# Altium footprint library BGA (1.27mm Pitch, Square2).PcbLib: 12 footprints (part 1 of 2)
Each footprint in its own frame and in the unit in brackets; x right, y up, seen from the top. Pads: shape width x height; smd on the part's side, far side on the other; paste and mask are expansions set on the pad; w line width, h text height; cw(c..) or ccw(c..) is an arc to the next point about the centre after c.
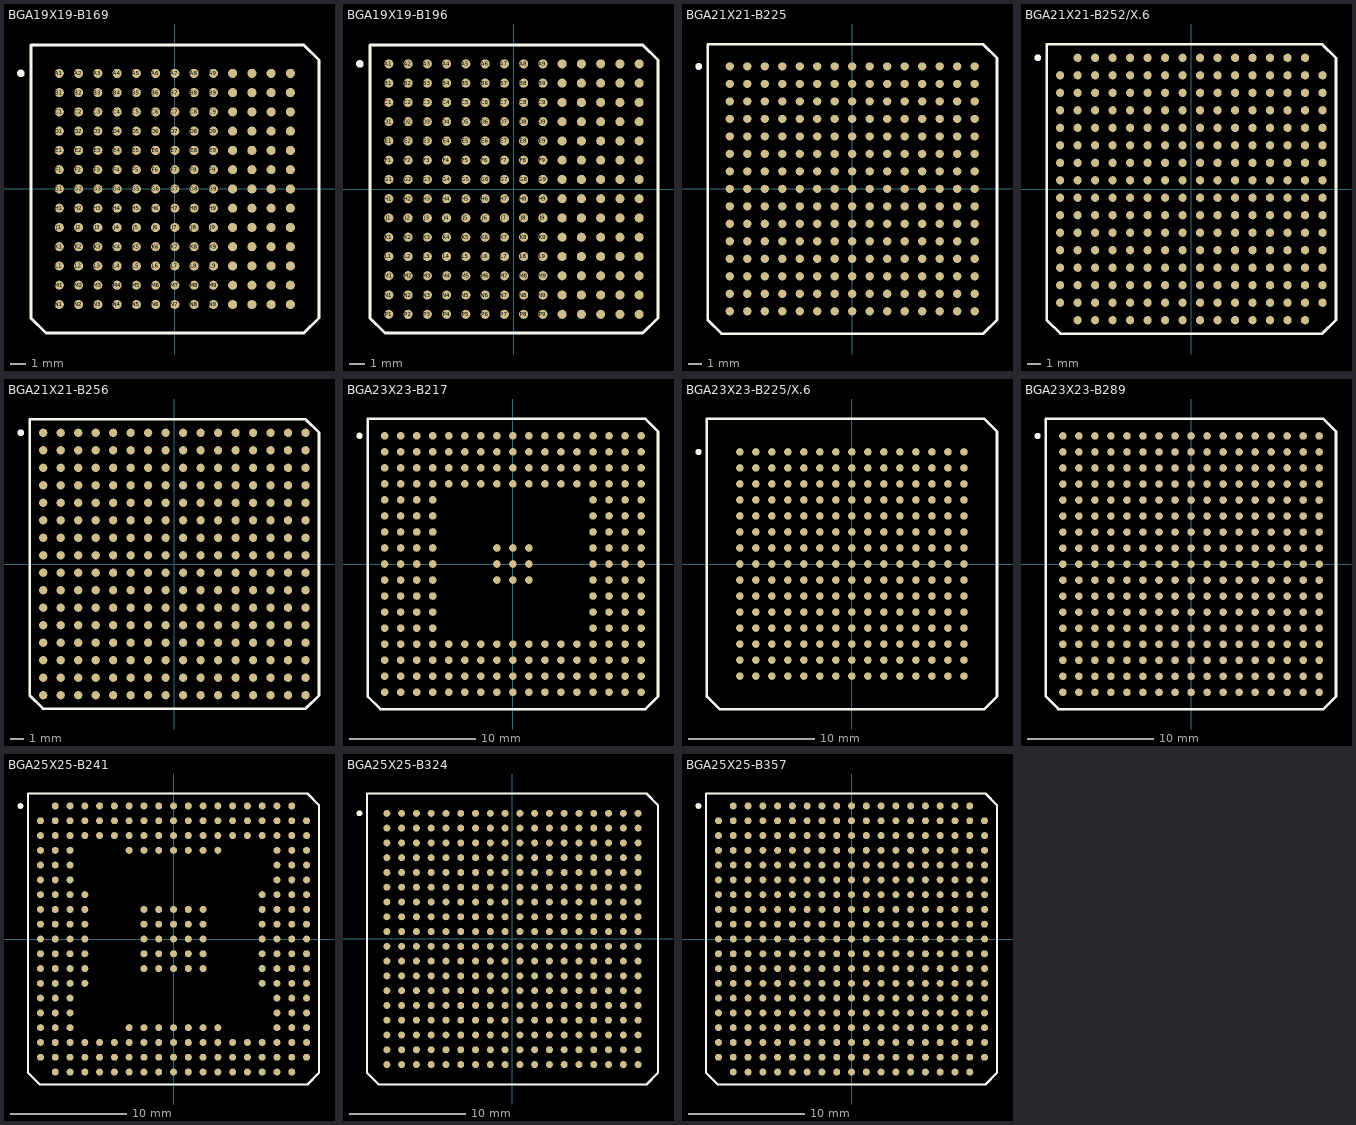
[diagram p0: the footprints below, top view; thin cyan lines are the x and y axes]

## BGA19X19-B169 [mm]
pads (169):
  round 0.6 smd: A1(-7.62,7.62) A2(-6.35,7.62) A3(-5.08,7.62) A4(-3.81,7.62) A5(-2.54,7.62) A6(-1.27,7.62) A7(0,7.62) A8(1.27,7.62) A9(2.54,7.62) A10(3.81,7.62) A11(5.08,7.62) A12(6.35,7.62) A13(7.62,7.62) B1(-7.62,6.35) B2(-6.35,6.35) B3(-5.08,6.35) B4(-3.81,6.35) B5(-2.54,6.35) B6(-1.27,6.35) B7(0,6.35) B8(1.27,6.35) B9(2.54,6.35) B10(3.81,6.35) B11(5.08,6.35) B12(6.35,6.35) B13(7.62,6.35) C1(-7.62,5.08) C2(-6.35,5.08) C3(-5.08,5.08) C4(-3.81,5.08) C5(-2.54,5.08) C6(-1.27,5.08) C7(0,5.08) C8(1.27,5.08) C9(2.54,5.08) C10(3.81,5.08) C11(5.08,5.08) C12(6.35,5.08) C13(7.62,5.08) D1(-7.62,3.81) D2(-6.35,3.81) D3(-5.08,3.81) D4(-3.81,3.81) D5(-2.54,3.81) D6(-1.27,3.81) D7(0,3.81) D8(1.27,3.81) D9(2.54,3.81) D10(3.81,3.81) D11(5.08,3.81) D12(6.35,3.81) D13(7.62,3.81) E1(-7.62,2.54) E2(-6.35,2.54) E3(-5.08,2.54) E4(-3.81,2.54) E5(-2.54,2.54) E6(-1.27,2.54) E7(0,2.54) E8(1.27,2.54) E9(2.54,2.54) E10(3.81,2.54) E11(5.08,2.54) E12(6.35,2.54) E13(7.62,2.54) F1(-7.62,1.27) F2(-6.35,1.27) F3(-5.08,1.27) F4(-3.81,1.27) F5(-2.54,1.27) F6(-1.27,1.27) F7(0,1.27) F8(1.27,1.27) F9(2.54,1.27) F10(3.81,1.27) F11(5.08,1.27) F12(6.35,1.27) F13(7.62,1.27) G1(-7.62,0) G2(-6.35,0) G3(-5.08,0) G4(-3.81,0) G5(-2.54,0) G6(-1.27,0) G7(0,0) G8(1.27,0) G9(2.54,0) G10(3.81,0) G11(5.08,0) G12(6.35,0) G13(7.62,0) H1(-7.62,-1.27) H2(-6.35,-1.27) H3(-5.08,-1.27) H4(-3.81,-1.27) H5(-2.54,-1.27) H6(-1.27,-1.27) H7(0,-1.27) H8(1.27,-1.27) H9(2.54,-1.27) H10(3.81,-1.27) H11(5.08,-1.27) H12(6.35,-1.27) H13(7.62,-1.27) J1(-7.62,-2.54) J2(-6.35,-2.54) J3(-5.08,-2.54) J4(-3.81,-2.54) J5(-2.54,-2.54) J6(-1.27,-2.54) J7(0,-2.54) J8(1.27,-2.54) J9(2.54,-2.54) J10(3.81,-2.54) J11(5.08,-2.54) J12(6.35,-2.54) J13(7.62,-2.54) K1(-7.62,-3.81) K2(-6.35,-3.81) K3(-5.08,-3.81) K4(-3.81,-3.81) K5(-2.54,-3.81) K6(-1.27,-3.81) K7(0,-3.81) K8(1.27,-3.81) K9(2.54,-3.81) K10(3.81,-3.81) K11(5.08,-3.81) K12(6.35,-3.81) K13(7.62,-3.81) L1(-7.62,-5.08) L2(-6.35,-5.08) L3(-5.08,-5.08) L4(-3.81,-5.08) L5(-2.54,-5.08) L6(-1.27,-5.08) L7(0,-5.08) L8(1.27,-5.08) L9(2.54,-5.08) L10(3.81,-5.08) L11(5.08,-5.08) L12(6.35,-5.08) L13(7.62,-5.08) M1(-7.62,-6.35) M2(-6.35,-6.35) M3(-5.08,-6.35) M4(-3.81,-6.35) M5(-2.54,-6.35) M6(-1.27,-6.35) M7(0,-6.35) M8(1.27,-6.35) M9(2.54,-6.35) M10(3.81,-6.35) M11(5.08,-6.35) M12(6.35,-6.35) M13(7.62,-6.35) N1(-7.62,-7.62) N2(-6.35,-7.62) N3(-5.08,-7.62) N4(-3.81,-7.62) N5(-2.54,-7.62) N6(-1.27,-7.62) N7(0,-7.62) N8(1.27,-7.62) N9(2.54,-7.62) N10(3.81,-7.62) N11(5.08,-7.62) N12(6.35,-7.62) N13(7.62,-7.62)
Top Overlay:
  circle w0.25: c-10.15,7.62 r0.125
  lines w0.2: -9.495,-8.505 -9.495,9.495 8.505,9.495 9.505,8.495 9.505,-8.505 8.505,-9.505 -8.495,-9.505 -9.495,-8.505

## BGA19X19-B196 [mm]
pads (196):
  round 0.6 smd: A1(-8.255,8.255) A2(-6.985,8.255) A3(-5.715,8.255) A4(-4.445,8.255) A5(-3.175,8.255) A6(-1.905,8.255) A7(-0.635,8.255) A8(0.635,8.255) A9(1.905,8.255) A10(3.175,8.255) A11(4.445,8.255) A12(5.715,8.255) A13(6.985,8.255) A14(8.255,8.255) B1(-8.255,6.985) B2(-6.985,6.985) B3(-5.715,6.985) B4(-4.445,6.985) B5(-3.175,6.985) B6(-1.905,6.985) B7(-0.635,6.985) B8(0.635,6.985) B9(1.905,6.985) B10(3.175,6.985) B11(4.445,6.985) B12(5.715,6.985) B13(6.985,6.985) B14(8.255,6.985) C1(-8.255,5.715) C2(-6.985,5.715) C3(-5.715,5.715) C4(-4.445,5.715) C5(-3.175,5.715) C6(-1.905,5.715) C7(-0.635,5.715) C8(0.635,5.715) C9(1.905,5.715) C10(3.175,5.715) C11(4.445,5.715) C12(5.715,5.715) C13(6.985,5.715) C14(8.255,5.715) D1(-8.255,4.445) D2(-6.985,4.445) D3(-5.715,4.445) D4(-4.445,4.445) D5(-3.175,4.445) D6(-1.905,4.445) D7(-0.635,4.445) D8(0.635,4.445) D9(1.905,4.445) D10(3.175,4.445) D11(4.445,4.445) D12(5.715,4.445) D13(6.985,4.445) D14(8.255,4.445) E1(-8.255,3.175) E2(-6.985,3.175) E3(-5.715,3.175) E4(-4.445,3.175) E5(-3.175,3.175) E6(-1.905,3.175) E7(-0.635,3.175) E8(0.635,3.175) E9(1.905,3.175) E10(3.175,3.175) E11(4.445,3.175) E12(5.715,3.175) E13(6.985,3.175) E14(8.255,3.175) F1(-8.255,1.905) F2(-6.985,1.905) F3(-5.715,1.905) F4(-4.445,1.905) F5(-3.175,1.905) F6(-1.905,1.905) F7(-0.635,1.905) F8(0.635,1.905) F9(1.905,1.905) F10(3.175,1.905) F11(4.445,1.905) F12(5.715,1.905) F13(6.985,1.905) F14(8.255,1.905) G1(-8.255,0.635) G2(-6.985,0.635) G3(-5.715,0.635) G4(-4.445,0.635) G5(-3.175,0.635) G6(-1.905,0.635) G7(-0.635,0.635) G8(0.635,0.635) G9(1.905,0.635) G10(3.175,0.635) G11(4.445,0.635) G12(5.715,0.635) G13(6.985,0.635) G14(8.255,0.635) H1(-8.255,-0.635) H2(-6.985,-0.635) H3(-5.715,-0.635) H4(-4.445,-0.635) H5(-3.175,-0.635) H6(-1.905,-0.635) H7(-0.635,-0.635) H8(0.635,-0.635) H9(1.905,-0.635) H10(3.175,-0.635) H11(4.445,-0.635) H12(5.715,-0.635) H13(6.985,-0.635) H14(8.255,-0.635) J1(-8.255,-1.905) J2(-6.985,-1.905) J3(-5.715,-1.905) J4(-4.445,-1.905) J5(-3.175,-1.905) J6(-1.905,-1.905) J7(-0.635,-1.905) J8(0.635,-1.905) J9(1.905,-1.905) J10(3.175,-1.905) J11(4.445,-1.905) J12(5.715,-1.905) J13(6.985,-1.905) J14(8.255,-1.905) K1(-8.255,-3.175) K2(-6.985,-3.175) K3(-5.715,-3.175) K4(-4.445,-3.175) K5(-3.175,-3.175) K6(-1.905,-3.175) K7(-0.635,-3.175) K8(0.635,-3.175) K9(1.905,-3.175) K10(3.175,-3.175) K11(4.445,-3.175) K12(5.715,-3.175) K13(6.985,-3.175) K14(8.255,-3.175) L1(-8.255,-4.445) L2(-6.985,-4.445) L3(-5.715,-4.445) L4(-4.445,-4.445) L5(-3.175,-4.445) L6(-1.905,-4.445) L7(-0.635,-4.445) L8(0.635,-4.445) L9(1.905,-4.445) L10(3.175,-4.445) L11(4.445,-4.445) L12(5.715,-4.445) L13(6.985,-4.445) L14(8.255,-4.445) M1(-8.255,-5.715) M2(-6.985,-5.715) M3(-5.715,-5.715) M4(-4.445,-5.715) M5(-3.175,-5.715) M6(-1.905,-5.715) M7(-0.635,-5.715) M8(0.635,-5.715) M9(1.905,-5.715) M10(3.175,-5.715) M11(4.445,-5.715) M12(5.715,-5.715) M13(6.985,-5.715) M14(8.255,-5.715) N1(-8.255,-6.985) N2(-6.985,-6.985) N3(-5.715,-6.985) N4(-4.445,-6.985) N5(-3.175,-6.985) N6(-1.905,-6.985) N7(-0.635,-6.985) N8(0.635,-6.985) N9(1.905,-6.985) N10(3.175,-6.985) N11(4.445,-6.985) N12(5.715,-6.985) N13(6.985,-6.985) N14(8.255,-6.985) P1(-8.255,-8.255) P2(-6.985,-8.255) P3(-5.715,-8.255) P4(-4.445,-8.255) P5(-3.175,-8.255) P6(-1.905,-8.255) P7(-0.635,-8.255) P8(0.635,-8.255) P9(1.905,-8.255) P10(3.175,-8.255) P11(4.445,-8.255) P12(5.715,-8.255) P13(6.985,-8.255) P14(8.255,-8.255)
Top Overlay:
  circle w0.25: c-10.16,8.255 r0.125
  lines w0.2: -9.505,-8.495 -9.505,9.505 8.495,9.505 9.495,8.505 9.495,-8.495 8.495,-9.495 -8.505,-9.495 -9.505,-8.495

## BGA21X21-B225 [mm]
pads (225):
  round 0.6 smd: A1(-8.89,8.89) A2(-7.62,8.89) A3(-6.35,8.89) A4(-5.08,8.89) A5(-3.81,8.89) A6(-2.54,8.89) A7(-1.27,8.89) A8(0,8.89) A9(1.27,8.89) A10(2.54,8.89) A11(3.81,8.89) A12(5.08,8.89) A13(6.35,8.89) A14(7.62,8.89) A15(8.89,8.89) B1(-8.89,7.62) B2(-7.62,7.62) B3(-6.35,7.62) B4(-5.08,7.62) B5(-3.81,7.62) B6(-2.54,7.62) B7(-1.27,7.62) B8(0,7.62) B9(1.27,7.62) B10(2.54,7.62) B11(3.81,7.62) B12(5.08,7.62) B13(6.35,7.62) B14(7.62,7.62) B15(8.89,7.62) C1(-8.89,6.35) C2(-7.62,6.35) C3(-6.35,6.35) C4(-5.08,6.35) C5(-3.81,6.35) C6(-2.54,6.35) C7(-1.27,6.35) C8(0,6.35) C9(1.27,6.35) C10(2.54,6.35) C11(3.81,6.35) C12(5.08,6.35) C13(6.35,6.35) C14(7.62,6.35) C15(8.89,6.35) D1(-8.89,5.08) D2(-7.62,5.08) D3(-6.35,5.08) D4(-5.08,5.08) D5(-3.81,5.08) D6(-2.54,5.08) D7(-1.27,5.08) D8(0,5.08) D9(1.27,5.08) D10(2.54,5.08) D11(3.81,5.08) D12(5.08,5.08) D13(6.35,5.08) D14(7.62,5.08) D15(8.89,5.08) E1(-8.89,3.81) E2(-7.62,3.81) E3(-6.35,3.81) E4(-5.08,3.81) E5(-3.81,3.81) E6(-2.54,3.81) E7(-1.27,3.81) E8(0,3.81) E9(1.27,3.81) E10(2.54,3.81) E11(3.81,3.81) E12(5.08,3.81) E13(6.35,3.81) E14(7.62,3.81) E15(8.89,3.81) F1(-8.89,2.54) F2(-7.62,2.54) F3(-6.35,2.54) F4(-5.08,2.54) F5(-3.81,2.54) F6(-2.54,2.54) F7(-1.27,2.54) F8(0,2.54) F9(1.27,2.54) F10(2.54,2.54) F11(3.81,2.54) F12(5.08,2.54) F13(6.35,2.54) F14(7.62,2.54) F15(8.89,2.54) G1(-8.89,1.27) G2(-7.62,1.27) G3(-6.35,1.27) G4(-5.08,1.27) G5(-3.81,1.27) G6(-2.54,1.27) G7(-1.27,1.27) G8(0,1.27) G9(1.27,1.27) G10(2.54,1.27) G11(3.81,1.27) G12(5.08,1.27) G13(6.35,1.27) G14(7.62,1.27) G15(8.89,1.27) H1(-8.89,0) H2(-7.62,0) H3(-6.35,0) H4(-5.08,0) H5(-3.81,0) H6(-2.54,0) H7(-1.27,0) H8(0,0) H9(1.27,0) H10(2.54,0) H11(3.81,0) H12(5.08,0) H13(6.35,0) H14(7.62,0) H15(8.89,0) J1(-8.89,-1.27) J2(-7.62,-1.27) J3(-6.35,-1.27) J4(-5.08,-1.27) J5(-3.81,-1.27) J6(-2.54,-1.27) J7(-1.27,-1.27) J8(0,-1.27) J9(1.27,-1.27) J10(2.54,-1.27) J11(3.81,-1.27) J12(5.08,-1.27) J13(6.35,-1.27) J14(7.62,-1.27) J15(8.89,-1.27) K1(-8.89,-2.54) K2(-7.62,-2.54) K3(-6.35,-2.54) K4(-5.08,-2.54) K5(-3.81,-2.54) K6(-2.54,-2.54) K7(-1.27,-2.54) K8(0,-2.54) K9(1.27,-2.54) K10(2.54,-2.54) K11(3.81,-2.54) K12(5.08,-2.54) K13(6.35,-2.54) K14(7.62,-2.54) K15(8.89,-2.54) L1(-8.89,-3.81) L2(-7.62,-3.81) L3(-6.35,-3.81) L4(-5.08,-3.81) L5(-3.81,-3.81) L6(-2.54,-3.81) L7(-1.27,-3.81) L8(0,-3.81) L9(1.27,-3.81) L10(2.54,-3.81) L11(3.81,-3.81) L12(5.08,-3.81) L13(6.35,-3.81) L14(7.62,-3.81) L15(8.89,-3.81) M1(-8.89,-5.08) M2(-7.62,-5.08) M3(-6.35,-5.08) M4(-5.08,-5.08) M5(-3.81,-5.08) M6(-2.54,-5.08) M7(-1.27,-5.08) M8(0,-5.08) M9(1.27,-5.08) M10(2.54,-5.08) M11(3.81,-5.08) M12(5.08,-5.08) M13(6.35,-5.08) M14(7.62,-5.08) M15(8.89,-5.08) N1(-8.89,-6.35) N2(-7.62,-6.35) N3(-6.35,-6.35) N4(-5.08,-6.35) N5(-3.81,-6.35) N6(-2.54,-6.35) N7(-1.27,-6.35) N8(0,-6.35) N9(1.27,-6.35) N10(2.54,-6.35) N11(3.81,-6.35) N12(5.08,-6.35) N13(6.35,-6.35) N14(7.62,-6.35) N15(8.89,-6.35) P1(-8.89,-7.62) P2(-7.62,-7.62) P3(-6.35,-7.62) P4(-5.08,-7.62) P5(-3.81,-7.62) P6(-2.54,-7.62) P7(-1.27,-7.62) P8(0,-7.62) P9(1.27,-7.62) P10(2.54,-7.62) P11(3.81,-7.62) P12(5.08,-7.62) P13(6.35,-7.62) P14(7.62,-7.62) P15(8.89,-7.62) R1(-8.89,-8.89) R2(-7.62,-8.89) R3(-6.35,-8.89) R4(-5.08,-8.89) R5(-3.81,-8.89) R6(-2.54,-8.89) R7(-1.27,-8.89) R8(0,-8.89) R9(1.27,-8.89) R10(2.54,-8.89) R11(3.81,-8.89) R12(5.08,-8.89) R13(6.35,-8.89) R14(7.62,-8.89) R15(8.89,-8.89)
Top Overlay:
  circle w0.25: c-11.145,8.89 r0.125
  lines w0.2: -10.49,-9.51 -9.49,-10.51 9.51,-10.51 10.51,-9.51 10.51,9.49 9.51,10.49 -10.49,10.49 -10.49,-9.51

## BGA21X21-B252/X.6 [mm]
pads (252):
  round 0.6 smd: A2(-8.255,9.525) A3(-6.985,9.525) A4(-5.715,9.525) A5(-4.445,9.525) A6(-3.175,9.525) A7(-1.905,9.525) A8(-0.635,9.525) A9(0.635,9.525) A10(1.905,9.525) A11(3.175,9.525) A12(4.445,9.525) A13(5.715,9.525) A14(6.985,9.525) A15(8.255,9.525) B1(-9.525,8.255) B2(-8.255,8.255) B3(-6.985,8.255) B4(-5.715,8.255) B5(-4.445,8.255) B6(-3.175,8.255) B7(-1.905,8.255) B8(-0.635,8.255) B9(0.635,8.255) B10(1.905,8.255) B11(3.175,8.255) B12(4.445,8.255) B13(5.715,8.255) B14(6.985,8.255) B15(8.255,8.255) B16(9.525,8.255) C1(-9.525,6.985) C2(-8.255,6.985) C3(-6.985,6.985) C4(-5.715,6.985) C5(-4.445,6.985) C6(-3.175,6.985) C7(-1.905,6.985) C8(-0.635,6.985) C9(0.635,6.985) C10(1.905,6.985) C11(3.175,6.985) C12(4.445,6.985) C13(5.715,6.985) C14(6.985,6.985) C15(8.255,6.985) C16(9.525,6.985) D1(-9.525,5.715) D2(-8.255,5.715) D3(-6.985,5.715) D4(-5.715,5.715) D5(-4.445,5.715) D6(-3.175,5.715) D7(-1.905,5.715) D8(-0.635,5.715) D9(0.635,5.715) D10(1.905,5.715) D11(3.175,5.715) D12(4.445,5.715) D13(5.715,5.715) D14(6.985,5.715) D15(8.255,5.715) D16(9.525,5.715) E1(-9.525,4.445) E2(-8.255,4.445) E3(-6.985,4.445) E4(-5.715,4.445) E5(-4.445,4.445) E6(-3.175,4.445) E7(-1.905,4.445) E8(-0.635,4.445) E9(0.635,4.445) E10(1.905,4.445) E11(3.175,4.445) E12(4.445,4.445) E13(5.715,4.445) E14(6.985,4.445) E15(8.255,4.445) E16(9.525,4.445) F1(-9.525,3.175) F2(-8.255,3.175) F3(-6.985,3.175) F4(-5.715,3.175) F5(-4.445,3.175) F6(-3.175,3.175) F7(-1.905,3.175) F8(-0.635,3.175) F9(0.635,3.175) F10(1.905,3.175) F11(3.175,3.175) F12(4.445,3.175) F13(5.715,3.175) F14(6.985,3.175) F15(8.255,3.175) F16(9.525,3.175) G1(-9.525,1.905) G2(-8.255,1.905) G3(-6.985,1.905) G4(-5.715,1.905) G5(-4.445,1.905) G6(-3.175,1.905) G7(-1.905,1.905) G8(-0.635,1.905) G9(0.635,1.905) G10(1.905,1.905) G11(3.175,1.905) G12(4.445,1.905) G13(5.715,1.905) G14(6.985,1.905) G15(8.255,1.905) G16(9.525,1.905) H1(-9.525,0.635) H2(-8.255,0.635) H3(-6.985,0.635) H4(-5.715,0.635) H5(-4.445,0.635) H6(-3.175,0.635) H7(-1.905,0.635) H8(-0.635,0.635) H9(0.635,0.635) H10(1.905,0.635) H11(3.175,0.635) H12(4.445,0.635) H13(5.715,0.635) H14(6.985,0.635) H15(8.255,0.635) H16(9.525,0.635) J1(-9.525,-0.635) J2(-8.255,-0.635) J3(-6.985,-0.635) J4(-5.715,-0.635) J5(-4.445,-0.635) J6(-3.175,-0.635) J7(-1.905,-0.635) J8(-0.635,-0.635) J9(0.635,-0.635) J10(1.905,-0.635) J11(3.175,-0.635) J12(4.445,-0.635) J13(5.715,-0.635) J14(6.985,-0.635) J15(8.255,-0.635) J16(9.525,-0.635) K1(-9.525,-1.905) K2(-8.255,-1.905) K3(-6.985,-1.905) K4(-5.715,-1.905) K5(-4.445,-1.905) K6(-3.175,-1.905) K7(-1.905,-1.905) K8(-0.635,-1.905) K9(0.635,-1.905) K10(1.905,-1.905) K11(3.175,-1.905) K12(4.445,-1.905) K13(5.715,-1.905) K14(6.985,-1.905) K15(8.255,-1.905) K16(9.525,-1.905) L1(-9.525,-3.175) L2(-8.255,-3.175) L3(-6.985,-3.175) L4(-5.715,-3.175) L5(-4.445,-3.175) L6(-3.175,-3.175) L7(-1.905,-3.175) L8(-0.635,-3.175) L9(0.635,-3.175) L10(1.905,-3.175) L11(3.175,-3.175) L12(4.445,-3.175) L13(5.715,-3.175) L14(6.985,-3.175) L15(8.255,-3.175) L16(9.525,-3.175) M1(-9.525,-4.445) M2(-8.255,-4.445) M3(-6.985,-4.445) M4(-5.715,-4.445) M5(-4.445,-4.445) M6(-3.175,-4.445) M7(-1.905,-4.445) M8(-0.635,-4.445) M9(0.635,-4.445) M10(1.905,-4.445) M11(3.175,-4.445) M12(4.445,-4.445) M13(5.715,-4.445) M14(6.985,-4.445) M15(8.255,-4.445) M16(9.525,-4.445) N1(-9.525,-5.715) N2(-8.255,-5.715) N3(-6.985,-5.715) N4(-5.715,-5.715) N5(-4.445,-5.715) N6(-3.175,-5.715) N7(-1.905,-5.715) N8(-0.635,-5.715) N9(0.635,-5.715) N10(1.905,-5.715) N11(3.175,-5.715) N12(4.445,-5.715) N13(5.715,-5.715) N14(6.985,-5.715) N15(8.255,-5.715) N16(9.525,-5.715) P1(-9.525,-6.985) P2(-8.255,-6.985) P3(-6.985,-6.985) P4(-5.715,-6.985) P5(-4.445,-6.985) P6(-3.175,-6.985) P7(-1.905,-6.985) P8(-0.635,-6.985) P9(0.635,-6.985) P10(1.905,-6.985) P11(3.175,-6.985) P12(4.445,-6.985) P13(5.715,-6.985) P14(6.985,-6.985) P15(8.255,-6.985) P16(9.525,-6.985) R1(-9.525,-8.255) R2(-8.255,-8.255) R3(-6.985,-8.255) R4(-5.715,-8.255) R5(-4.445,-8.255) R6(-3.175,-8.255) R7(-1.905,-8.255) R8(-0.635,-8.255) R9(0.635,-8.255) R10(1.905,-8.255) R11(3.175,-8.255) R12(4.445,-8.255) R13(5.715,-8.255) R14(6.985,-8.255) R15(8.255,-8.255) R16(9.525,-8.255) T2(-8.255,-9.525) T3(-6.985,-9.525) T4(-5.715,-9.525) T5(-4.445,-9.525) T6(-3.175,-9.525) T7(-1.905,-9.525) T8(-0.635,-9.525) T9(0.635,-9.525) T10(1.905,-9.525) T11(3.175,-9.525) T12(4.445,-9.525) T13(5.715,-9.525) T14(6.985,-9.525) T15(8.255,-9.525)
Top Overlay:
  circle w0.25: c-11.15,9.525 r0.125
  lines w0.2: -10.5,-9.5 -9.5,-10.5 9.5,-10.5 10.5,-9.5 10.5,9.5 9.5,10.5 -10.5,10.5 -10.5,-9.5

## BGA21X21-B256 [mm]
pads (256):
  round 0.6 smd: A1(-9.525,9.525) A2(-8.255,9.525) A3(-6.985,9.525) A4(-5.715,9.525) A5(-4.445,9.525) A6(-3.175,9.525) A7(-1.905,9.525) A8(-0.635,9.525) A9(0.635,9.525) A10(1.905,9.525) A11(3.175,9.525) A12(4.445,9.525) A13(5.715,9.525) A14(6.985,9.525) A15(8.255,9.525) A16(9.525,9.525) B1(-9.525,8.255) B2(-8.255,8.255) B3(-6.985,8.255) B4(-5.715,8.255) B5(-4.445,8.255) B6(-3.175,8.255) B7(-1.905,8.255) B8(-0.635,8.255) B9(0.635,8.255) B10(1.905,8.255) B11(3.175,8.255) B12(4.445,8.255) B13(5.715,8.255) B14(6.985,8.255) B15(8.255,8.255) B16(9.525,8.255) C1(-9.525,6.985) C2(-8.255,6.985) C3(-6.985,6.985) C4(-5.715,6.985) C5(-4.445,6.985) C6(-3.175,6.985) C7(-1.905,6.985) C8(-0.635,6.985) C9(0.635,6.985) C10(1.905,6.985) C11(3.175,6.985) C12(4.445,6.985) C13(5.715,6.985) C14(6.985,6.985) C15(8.255,6.985) C16(9.525,6.985) D1(-9.525,5.715) D2(-8.255,5.715) D3(-6.985,5.715) D4(-5.715,5.715) D5(-4.445,5.715) D6(-3.175,5.715) D7(-1.905,5.715) D8(-0.635,5.715) D9(0.635,5.715) D10(1.905,5.715) D11(3.175,5.715) D12(4.445,5.715) D13(5.715,5.715) D14(6.985,5.715) D15(8.255,5.715) D16(9.525,5.715) E1(-9.525,4.445) E2(-8.255,4.445) E3(-6.985,4.445) E4(-5.715,4.445) E5(-4.445,4.445) E6(-3.175,4.445) E7(-1.905,4.445) E8(-0.635,4.445) E9(0.635,4.445) E10(1.905,4.445) E11(3.175,4.445) E12(4.445,4.445) E13(5.715,4.445) E14(6.985,4.445) E15(8.255,4.445) E16(9.525,4.445) F1(-9.525,3.175) F2(-8.255,3.175) F3(-6.985,3.175) F4(-5.715,3.175) F5(-4.445,3.175) F6(-3.175,3.175) F7(-1.905,3.175) F8(-0.635,3.175) F9(0.635,3.175) F10(1.905,3.175) F11(3.175,3.175) F12(4.445,3.175) F13(5.715,3.175) F14(6.985,3.175) F15(8.255,3.175) F16(9.525,3.175) G1(-9.525,1.905) G2(-8.255,1.905) G3(-6.985,1.905) G4(-5.715,1.905) G5(-4.445,1.905) G6(-3.175,1.905) G7(-1.905,1.905) G8(-0.635,1.905) G9(0.635,1.905) G10(1.905,1.905) G11(3.175,1.905) G12(4.445,1.905) G13(5.715,1.905) G14(6.985,1.905) G15(8.255,1.905) G16(9.525,1.905) H1(-9.525,0.635) H2(-8.255,0.635) H3(-6.985,0.635) H4(-5.715,0.635) H5(-4.445,0.635) H6(-3.175,0.635) H7(-1.905,0.635) H8(-0.635,0.635) H9(0.635,0.635) H10(1.905,0.635) H11(3.175,0.635) H12(4.445,0.635) H13(5.715,0.635) H14(6.985,0.635) H15(8.255,0.635) H16(9.525,0.635) J1(-9.525,-0.635) J2(-8.255,-0.635) J3(-6.985,-0.635) J4(-5.715,-0.635) J5(-4.445,-0.635) J6(-3.175,-0.635) J7(-1.905,-0.635) J8(-0.635,-0.635) J9(0.635,-0.635) J10(1.905,-0.635) J11(3.175,-0.635) J12(4.445,-0.635) J13(5.715,-0.635) J14(6.985,-0.635) J15(8.255,-0.635) J16(9.525,-0.635) K1(-9.525,-1.905) K2(-8.255,-1.905) K3(-6.985,-1.905) K4(-5.715,-1.905) K5(-4.445,-1.905) K6(-3.175,-1.905) K7(-1.905,-1.905) K8(-0.635,-1.905) K9(0.635,-1.905) K10(1.905,-1.905) K11(3.175,-1.905) K12(4.445,-1.905) K13(5.715,-1.905) K14(6.985,-1.905) K15(8.255,-1.905) K16(9.525,-1.905) L1(-9.525,-3.175) L2(-8.255,-3.175) L3(-6.985,-3.175) L4(-5.715,-3.175) L5(-4.445,-3.175) L6(-3.175,-3.175) L7(-1.905,-3.175) L8(-0.635,-3.175) L9(0.635,-3.175) L10(1.905,-3.175) L11(3.175,-3.175) L12(4.445,-3.175) L13(5.715,-3.175) L14(6.985,-3.175) L15(8.255,-3.175) L16(9.525,-3.175) M1(-9.525,-4.445) M2(-8.255,-4.445) M3(-6.985,-4.445) M4(-5.715,-4.445) M5(-4.445,-4.445) M6(-3.175,-4.445) M7(-1.905,-4.445) M8(-0.635,-4.445) M9(0.635,-4.445) M10(1.905,-4.445) M11(3.175,-4.445) M12(4.445,-4.445) M13(5.715,-4.445) M14(6.985,-4.445) M15(8.255,-4.445) M16(9.525,-4.445) N1(-9.525,-5.715) N2(-8.255,-5.715) N3(-6.985,-5.715) N4(-5.715,-5.715) N5(-4.445,-5.715) N6(-3.175,-5.715) N7(-1.905,-5.715) N8(-0.635,-5.715) N9(0.635,-5.715) N10(1.905,-5.715) N11(3.175,-5.715) N12(4.445,-5.715) N13(5.715,-5.715) N14(6.985,-5.715) N15(8.255,-5.715) N16(9.525,-5.715) P1(-9.525,-6.985) P2(-8.255,-6.985) P3(-6.985,-6.985) P4(-5.715,-6.985) P5(-4.445,-6.985) P6(-3.175,-6.985) P7(-1.905,-6.985) P8(-0.635,-6.985) P9(0.635,-6.985) P10(1.905,-6.985) P11(3.175,-6.985) P12(4.445,-6.985) P13(5.715,-6.985) P14(6.985,-6.985) P15(8.255,-6.985) P16(9.525,-6.985) R1(-9.525,-8.255) R2(-8.255,-8.255) R3(-6.985,-8.255) R4(-5.715,-8.255) R5(-4.445,-8.255) R6(-3.175,-8.255) R7(-1.905,-8.255) R8(-0.635,-8.255) R9(0.635,-8.255) R10(1.905,-8.255) R11(3.175,-8.255) R12(4.445,-8.255) R13(5.715,-8.255) R14(6.985,-8.255) R15(8.255,-8.255) R16(9.525,-8.255) T1(-9.525,-9.525) T2(-8.255,-9.525) T3(-6.985,-9.525) T4(-5.715,-9.525) T5(-4.445,-9.525) T6(-3.175,-9.525) T7(-1.905,-9.525) T8(-0.635,-9.525) T9(0.635,-9.525) T10(1.905,-9.525) T11(3.175,-9.525) T12(4.445,-9.525) T13(5.715,-9.525) T14(6.985,-9.525) T15(8.255,-9.525) T16(9.525,-9.525)
Top Overlay:
  circle w0.25: c-11.155,9.525 r0.125
  lines w0.2: -10.5,-9.54 -10.5,10.5 9.54,10.5 10.5,9.54 10.5,-9.54 9.54,-10.5 -9.54,-10.5 -10.5,-9.54

## BGA23X23-B217 [mm]
pads (217):
  round 0.6 smd: A1(-10.16,10.16) A2(-8.89,10.16) A3(-7.62,10.16) A4(-6.35,10.16) A5(-5.08,10.16) A6(-3.81,10.16) A7(-2.54,10.16) A8(-1.27,10.16) A9(0,10.16) A10(1.27,10.16) A11(2.54,10.16) A12(3.81,10.16) A13(5.08,10.16) A14(6.35,10.16) A15(7.62,10.16) A16(8.89,10.16) A17(10.16,10.16) B1(-10.16,8.89) B2(-8.89,8.89) B3(-7.62,8.89) B4(-6.35,8.89) B5(-5.08,8.89) B6(-3.81,8.89) B7(-2.54,8.89) B8(-1.27,8.89) B9(0,8.89) B10(1.27,8.89) B11(2.54,8.89) B12(3.81,8.89) B13(5.08,8.89) B14(6.35,8.89) B15(7.62,8.89) B16(8.89,8.89) B17(10.16,8.89) C1(-10.16,7.62) C2(-8.89,7.62) C3(-7.62,7.62) C4(-6.35,7.62) C5(-5.08,7.62) C6(-3.81,7.62) C7(-2.54,7.62) C8(-1.27,7.62) C9(0,7.62) C10(1.27,7.62) C11(2.54,7.62) C12(3.81,7.62) C13(5.08,7.62) C14(6.35,7.62) C15(7.62,7.62) C16(8.89,7.62) C17(10.16,7.62) D1(-10.16,6.35) D2(-8.89,6.35) D3(-7.62,6.35) D4(-6.35,6.35) D5(-5.08,6.35) D6(-3.81,6.35) D7(-2.54,6.35) D8(-1.27,6.35) D9(0,6.35) D10(1.27,6.35) D11(2.54,6.35) D12(3.81,6.35) D13(5.08,6.35) D14(6.35,6.35) D15(7.62,6.35) D16(8.89,6.35) D17(10.16,6.35) E1(-10.16,5.08) E2(-8.89,5.08) E3(-7.62,5.08) E4(-6.35,5.08) E14(6.35,5.08) E15(7.62,5.08) E16(8.89,5.08) E17(10.16,5.08) F1(-10.16,3.81) F2(-8.89,3.81) F3(-7.62,3.81) F4(-6.35,3.81) F14(6.35,3.81) F15(7.62,3.81) F16(8.89,3.81) F17(10.16,3.81) G1(-10.16,2.54) G2(-8.89,2.54) G3(-7.62,2.54) G4(-6.35,2.54) G14(6.35,2.54) G15(7.62,2.54) G16(8.89,2.54) G17(10.16,2.54) H1(-10.16,1.27) H2(-8.89,1.27) H3(-7.62,1.27) H4(-6.35,1.27) H8(-1.27,1.27) H9(0,1.27) H10(1.27,1.27) H14(6.35,1.27) H15(7.62,1.27) H16(8.89,1.27) H17(10.16,1.27) J1(-10.16,0) J2(-8.89,0) J3(-7.62,0) J4(-6.35,0) J8(-1.27,0) J9(0,0) J10(1.27,0) J14(6.35,0) J15(7.62,0) J16(8.89,0) J17(10.16,0) K1(-10.16,-1.27) K2(-8.89,-1.27) K3(-7.62,-1.27) K4(-6.35,-1.27) K8(-1.27,-1.27) K9(0,-1.27) K10(1.27,-1.27) K14(6.35,-1.27) K15(7.62,-1.27) K16(8.89,-1.27) K17(10.16,-1.27) L1(-10.16,-2.54) L2(-8.89,-2.54) L3(-7.62,-2.54) L4(-6.35,-2.54) L14(6.35,-2.54) L15(7.62,-2.54) L16(8.89,-2.54) L17(10.16,-2.54) M1(-10.16,-3.81) M2(-8.89,-3.81) M3(-7.62,-3.81) M4(-6.35,-3.81) M14(6.35,-3.81) M15(7.62,-3.81) M16(8.89,-3.81) M17(10.16,-3.81) N1(-10.16,-5.08) N2(-8.89,-5.08) N3(-7.62,-5.08) N4(-6.35,-5.08) N14(6.35,-5.08) N15(7.62,-5.08) N16(8.89,-5.08) N17(10.16,-5.08) P1(-10.16,-6.35) P2(-8.89,-6.35) P3(-7.62,-6.35) P4(-6.35,-6.35) P5(-5.08,-6.35) P6(-3.81,-6.35) P7(-2.54,-6.35) P8(-1.27,-6.35) P9(0,-6.35) P10(1.27,-6.35) P11(2.54,-6.35) P12(3.81,-6.35) P13(5.08,-6.35) P14(6.35,-6.35) P15(7.62,-6.35) P16(8.89,-6.35) P17(10.16,-6.35) R1(-10.16,-7.62) R2(-8.89,-7.62) R3(-7.62,-7.62) R4(-6.35,-7.62) R5(-5.08,-7.62) R6(-3.81,-7.62) R7(-2.54,-7.62) R8(-1.27,-7.62) R9(0,-7.62) R10(1.27,-7.62) R11(2.54,-7.62) R12(3.81,-7.62) R13(5.08,-7.62) R14(6.35,-7.62) R15(7.62,-7.62) R16(8.89,-7.62) R17(10.16,-7.62) T1(-10.16,-8.89) T2(-8.89,-8.89) T3(-7.62,-8.89) T4(-6.35,-8.89) T5(-5.08,-8.89) T6(-3.81,-8.89) T7(-2.54,-8.89) T8(-1.27,-8.89) T9(0,-8.89) T10(1.27,-8.89) T11(2.54,-8.89) T12(3.81,-8.89) T13(5.08,-8.89) T14(6.35,-8.89) T15(7.62,-8.89) T16(8.89,-8.89) T17(10.16,-8.89) U1(-10.16,-10.16) U2(-8.89,-10.16) U3(-7.62,-10.16) U4(-6.35,-10.16) U5(-5.08,-10.16) U6(-3.81,-10.16) U7(-2.54,-10.16) U8(-1.27,-10.16) U9(0,-10.16) U10(1.27,-10.16) U11(2.54,-10.16) U12(3.81,-10.16) U13(5.08,-10.16) U14(6.35,-10.16) U15(7.62,-10.16) U16(8.89,-10.16) U17(10.16,-10.16)
Top Overlay:
  circle w0.25: c-12.15,10.16 r0.125
  lines w0.2: -11.5,-10.5 -10.5,-11.5 10.5,-11.5 11.5,-10.5 11.5,10.5 10.5,11.5 -11.5,11.5 -11.5,-10.5

## BGA23X23-B225/X.6 [mm]
pads (225):
  round 0.6 smd: A1(-8.89,8.89) A2(-7.62,8.89) A3(-6.35,8.89) A4(-5.08,8.89) A5(-3.81,8.89) A6(-2.54,8.89) A7(-1.27,8.89) A8(0,8.89) A9(1.27,8.89) A10(2.54,8.89) A11(3.81,8.89) A12(5.08,8.89) A13(6.35,8.89) A14(7.62,8.89) A15(8.89,8.89) B1(-8.89,7.62) B2(-7.62,7.62) B3(-6.35,7.62) B4(-5.08,7.62) B5(-3.81,7.62) B6(-2.54,7.62) B7(-1.27,7.62) B8(0,7.62) B9(1.27,7.62) B10(2.54,7.62) B11(3.81,7.62) B12(5.08,7.62) B13(6.35,7.62) B14(7.62,7.62) B15(8.89,7.62) C1(-8.89,6.35) C2(-7.62,6.35) C3(-6.35,6.35) C4(-5.08,6.35) C5(-3.81,6.35) C6(-2.54,6.35) C7(-1.27,6.35) C8(0,6.35) C9(1.27,6.35) C10(2.54,6.35) C11(3.81,6.35) C12(5.08,6.35) C13(6.35,6.35) C14(7.62,6.35) C15(8.89,6.35) D1(-8.89,5.08) D2(-7.62,5.08) D3(-6.35,5.08) D4(-5.08,5.08) D5(-3.81,5.08) D6(-2.54,5.08) D7(-1.27,5.08) D8(0,5.08) D9(1.27,5.08) D10(2.54,5.08) D11(3.81,5.08) D12(5.08,5.08) D13(6.35,5.08) D14(7.62,5.08) D15(8.89,5.08) E1(-8.89,3.81) E2(-7.62,3.81) E3(-6.35,3.81) E4(-5.08,3.81) E5(-3.81,3.81) E6(-2.54,3.81) E7(-1.27,3.81) E8(0,3.81) E9(1.27,3.81) E10(2.54,3.81) E11(3.81,3.81) E12(5.08,3.81) E13(6.35,3.81) E14(7.62,3.81) E15(8.89,3.81) F1(-8.89,2.54) F2(-7.62,2.54) F3(-6.35,2.54) F4(-5.08,2.54) F5(-3.81,2.54) F6(-2.54,2.54) F7(-1.27,2.54) F8(0,2.54) F9(1.27,2.54) F10(2.54,2.54) F11(3.81,2.54) F12(5.08,2.54) F13(6.35,2.54) F14(7.62,2.54) F15(8.89,2.54) G1(-8.89,1.27) G2(-7.62,1.27) G3(-6.35,1.27) G4(-5.08,1.27) G5(-3.81,1.27) G6(-2.54,1.27) G7(-1.27,1.27) G8(0,1.27) G9(1.27,1.27) G10(2.54,1.27) G11(3.81,1.27) G12(5.08,1.27) G13(6.35,1.27) G14(7.62,1.27) G15(8.89,1.27) H1(-8.89,0) H2(-7.62,0) H3(-6.35,0) H4(-5.08,0) H5(-3.81,0) H6(-2.54,0) H7(-1.27,0) H8(0,0) H9(1.27,0) H10(2.54,0) H11(3.81,0) H12(5.08,0) H13(6.35,0) H14(7.62,0) H15(8.89,0) J1(-8.89,-1.27) J2(-7.62,-1.27) J3(-6.35,-1.27) J4(-5.08,-1.27) J5(-3.81,-1.27) J6(-2.54,-1.27) J7(-1.27,-1.27) J8(0,-1.27) J9(1.27,-1.27) J10(2.54,-1.27) J11(3.81,-1.27) J12(5.08,-1.27) J13(6.35,-1.27) J14(7.62,-1.27) J15(8.89,-1.27) K1(-8.89,-2.54) K2(-7.62,-2.54) K3(-6.35,-2.54) K4(-5.08,-2.54) K5(-3.81,-2.54) K6(-2.54,-2.54) K7(-1.27,-2.54) K8(0,-2.54) K9(1.27,-2.54) K10(2.54,-2.54) K11(3.81,-2.54) K12(5.08,-2.54) K13(6.35,-2.54) K14(7.62,-2.54) K15(8.89,-2.54) L1(-8.89,-3.81) L2(-7.62,-3.81) L3(-6.35,-3.81) L4(-5.08,-3.81) L5(-3.81,-3.81) L6(-2.54,-3.81) L7(-1.27,-3.81) L8(0,-3.81) L9(1.27,-3.81) L10(2.54,-3.81) L11(3.81,-3.81) L12(5.08,-3.81) L13(6.35,-3.81) L14(7.62,-3.81) L15(8.89,-3.81) M1(-8.89,-5.08) M2(-7.62,-5.08) M3(-6.35,-5.08) M4(-5.08,-5.08) M5(-3.81,-5.08) M6(-2.54,-5.08) M7(-1.27,-5.08) M8(0,-5.08) M9(1.27,-5.08) M10(2.54,-5.08) M11(3.81,-5.08) M12(5.08,-5.08) M13(6.35,-5.08) M14(7.62,-5.08) M15(8.89,-5.08) N1(-8.89,-6.35) N2(-7.62,-6.35) N3(-6.35,-6.35) N4(-5.08,-6.35) N5(-3.81,-6.35) N6(-2.54,-6.35) N7(-1.27,-6.35) N8(0,-6.35) N9(1.27,-6.35) N10(2.54,-6.35) N11(3.81,-6.35) N12(5.08,-6.35) N13(6.35,-6.35) N14(7.62,-6.35) N15(8.89,-6.35) P1(-8.89,-7.62) P2(-7.62,-7.62) P3(-6.35,-7.62) P4(-5.08,-7.62) P5(-3.81,-7.62) P6(-2.54,-7.62) P7(-1.27,-7.62) P8(0,-7.62) P9(1.27,-7.62) P10(2.54,-7.62) P11(3.81,-7.62) P12(5.08,-7.62) P13(6.35,-7.62) P14(7.62,-7.62) P15(8.89,-7.62) R1(-8.89,-8.89) R2(-7.62,-8.89) R3(-6.35,-8.89) R4(-5.08,-8.89) R5(-3.81,-8.89) R6(-2.54,-8.89) R7(-1.27,-8.89) R8(0,-8.89) R9(1.27,-8.89) R10(2.54,-8.89) R11(3.81,-8.89) R12(5.08,-8.89) R13(6.35,-8.89) R14(7.62,-8.89) R15(8.89,-8.89)
Top Overlay:
  circle w0.25: c-12.16,8.89 r0.125
  lines w0.2: -11.51,-10.51 -11.49,-10.51 -10.49,-11.51 10.51,-11.51 11.51,-10.51 11.51,10.51 10.51,11.51 -11.51,11.51 -11.51,-10.51

## BGA23X23-B289 [mm]
pads (289):
  round 0.6 smd: A1(-10.16,10.16) A2(-8.89,10.16) A3(-7.62,10.16) A4(-6.35,10.16) A5(-5.08,10.16) A6(-3.81,10.16) A7(-2.54,10.16) A8(-1.27,10.16) A9(0,10.16) A10(1.27,10.16) A11(2.54,10.16) A12(3.81,10.16) A13(5.08,10.16) A14(6.35,10.16) A15(7.62,10.16) A16(8.89,10.16) A17(10.16,10.16) B1(-10.16,8.89) B2(-8.89,8.89) B3(-7.62,8.89) B4(-6.35,8.89) B5(-5.08,8.89) B6(-3.81,8.89) B7(-2.54,8.89) B8(-1.27,8.89) B9(0,8.89) B10(1.27,8.89) B11(2.54,8.89) B12(3.81,8.89) B13(5.08,8.89) B14(6.35,8.89) B15(7.62,8.89) B16(8.89,8.89) B17(10.16,8.89) C1(-10.16,7.62) C2(-8.89,7.62) C3(-7.62,7.62) C4(-6.35,7.62) C5(-5.08,7.62) C6(-3.81,7.62) C7(-2.54,7.62) C8(-1.27,7.62) C9(0,7.62) C10(1.27,7.62) C11(2.54,7.62) C12(3.81,7.62) C13(5.08,7.62) C14(6.35,7.62) C15(7.62,7.62) C16(8.89,7.62) C17(10.16,7.62) D1(-10.16,6.35) D2(-8.89,6.35) D3(-7.62,6.35) D4(-6.35,6.35) D5(-5.08,6.35) D6(-3.81,6.35) D7(-2.54,6.35) D8(-1.27,6.35) D9(0,6.35) D10(1.27,6.35) D11(2.54,6.35) D12(3.81,6.35) D13(5.08,6.35) D14(6.35,6.35) D15(7.62,6.35) D16(8.89,6.35) D17(10.16,6.35) E1(-10.16,5.08) E2(-8.89,5.08) E3(-7.62,5.08) E4(-6.35,5.08) E5(-5.08,5.08) E6(-3.81,5.08) E7(-2.54,5.08) E8(-1.27,5.08) E9(0,5.08) E10(1.27,5.08) E11(2.54,5.08) E12(3.81,5.08) E13(5.08,5.08) E14(6.35,5.08) E15(7.62,5.08) E16(8.89,5.08) E17(10.16,5.08) F1(-10.16,3.81) F2(-8.89,3.81) F3(-7.62,3.81) F4(-6.35,3.81) F5(-5.08,3.81) F6(-3.81,3.81) F7(-2.54,3.81) F8(-1.27,3.81) F9(0,3.81) F10(1.27,3.81) F11(2.54,3.81) F12(3.81,3.81) F13(5.08,3.81) F14(6.35,3.81) F15(7.62,3.81) F16(8.89,3.81) F17(10.16,3.81) G1(-10.16,2.54) G2(-8.89,2.54) G3(-7.62,2.54) G4(-6.35,2.54) G5(-5.08,2.54) G6(-3.81,2.54) G7(-2.54,2.54) G8(-1.27,2.54) G9(0,2.54) G10(1.27,2.54) G11(2.54,2.54) G12(3.81,2.54) G13(5.08,2.54) G14(6.35,2.54) G15(7.62,2.54) G16(8.89,2.54) G17(10.16,2.54) H1(-10.16,1.27) H2(-8.89,1.27) H3(-7.62,1.27) H4(-6.35,1.27) H5(-5.08,1.27) H6(-3.81,1.27) H7(-2.54,1.27) H8(-1.27,1.27) H9(0,1.27) H10(1.27,1.27) H11(2.54,1.27) H12(3.81,1.27) H13(5.08,1.27) H14(6.35,1.27) H15(7.62,1.27) H16(8.89,1.27) H17(10.16,1.27) J1(-10.16,0) J2(-8.89,0) J3(-7.62,0) J4(-6.35,0) J5(-5.08,0) J6(-3.81,0) J7(-2.54,0) J8(-1.27,0) J9(0,0) J10(1.27,0) J11(2.54,0) J12(3.81,0) J13(5.08,0) J14(6.35,0) J15(7.62,0) J16(8.89,0) J17(10.16,0) K1(-10.16,-1.27) K2(-8.89,-1.27) K3(-7.62,-1.27) K4(-6.35,-1.27) K5(-5.08,-1.27) K6(-3.81,-1.27) K7(-2.54,-1.27) K8(-1.27,-1.27) K9(0,-1.27) K10(1.27,-1.27) K11(2.54,-1.27) K12(3.81,-1.27) K13(5.08,-1.27) K14(6.35,-1.27) K15(7.62,-1.27) K16(8.89,-1.27) K17(10.16,-1.27) L1(-10.16,-2.54) L2(-8.89,-2.54) L3(-7.62,-2.54) L4(-6.35,-2.54) L5(-5.08,-2.54) L6(-3.81,-2.54) L7(-2.54,-2.54) L8(-1.27,-2.54) L9(0,-2.54) L10(1.27,-2.54) L11(2.54,-2.54) L12(3.81,-2.54) L13(5.08,-2.54) L14(6.35,-2.54) L15(7.62,-2.54) L16(8.89,-2.54) L17(10.16,-2.54) M1(-10.16,-3.81) M2(-8.89,-3.81) M3(-7.62,-3.81) M4(-6.35,-3.81) M5(-5.08,-3.81) M6(-3.81,-3.81) M7(-2.54,-3.81) M8(-1.27,-3.81) M9(0,-3.81) M10(1.27,-3.81) M11(2.54,-3.81) M12(3.81,-3.81) M13(5.08,-3.81) M14(6.35,-3.81) M15(7.62,-3.81) M16(8.89,-3.81) M17(10.16,-3.81) N1(-10.16,-5.08) N2(-8.89,-5.08) N3(-7.62,-5.08) N4(-6.35,-5.08) N5(-5.08,-5.08) N6(-3.81,-5.08) N7(-2.54,-5.08) N8(-1.27,-5.08) N9(0,-5.08) N10(1.27,-5.08) N11(2.54,-5.08) N12(3.81,-5.08) N13(5.08,-5.08) N14(6.35,-5.08) N15(7.62,-5.08) N16(8.89,-5.08) N17(10.16,-5.08) P1(-10.16,-6.35) P2(-8.89,-6.35) P3(-7.62,-6.35) P4(-6.35,-6.35) P5(-5.08,-6.35) P6(-3.81,-6.35) P7(-2.54,-6.35) P8(-1.27,-6.35) P9(0,-6.35) P10(1.27,-6.35) P11(2.54,-6.35) P12(3.81,-6.35) P13(5.08,-6.35) P14(6.35,-6.35) P15(7.62,-6.35) P16(8.89,-6.35) P17(10.16,-6.35) R1(-10.16,-7.62) R2(-8.89,-7.62) R3(-7.62,-7.62) R4(-6.35,-7.62) R5(-5.08,-7.62) R6(-3.81,-7.62) R7(-2.54,-7.62) R8(-1.27,-7.62) R9(0,-7.62) R10(1.27,-7.62) R11(2.54,-7.62) R12(3.81,-7.62) R13(5.08,-7.62) R14(6.35,-7.62) R15(7.62,-7.62) R16(8.89,-7.62) R17(10.16,-7.62) T1(-10.16,-8.89) T2(-8.89,-8.89) T3(-7.62,-8.89) T4(-6.35,-8.89) T5(-5.08,-8.89) T6(-3.81,-8.89) T7(-2.54,-8.89) T8(-1.27,-8.89) T9(0,-8.89) T10(1.27,-8.89) T11(2.54,-8.89) T12(3.81,-8.89) T13(5.08,-8.89) T14(6.35,-8.89) T15(7.62,-8.89) T16(8.89,-8.89) T17(10.16,-8.89) U1(-10.16,-10.16) U2(-8.89,-10.16) U3(-7.62,-10.16) U4(-6.35,-10.16) U5(-5.08,-10.16) U6(-3.81,-10.16) U7(-2.54,-10.16) U8(-1.27,-10.16) U9(0,-10.16) U10(1.27,-10.16) U11(2.54,-10.16) U12(3.81,-10.16) U13(5.08,-10.16) U14(6.35,-10.16) U15(7.62,-10.16) U16(8.89,-10.16) U17(10.16,-10.16)
Top Overlay:
  circle w0.25: c-12.165,10.16 r0.125
  lines w0.2: -11.51,-10.49 -10.51,-11.49 10.49,-11.49 11.49,-10.49 11.49,10.51 10.49,11.51 -11.51,11.51 -11.51,-10.49

## BGA25X25-B241 [mm]
pads (241):
  round 0.6 smd: A2(-10.16,11.43) A3(-8.89,11.43) A4(-7.62,11.43) A5(-6.35,11.43) A6(-5.08,11.43) A7(-3.81,11.43) A8(-2.54,11.43) A9(-1.27,11.43) A10(0,11.43) A11(1.27,11.43) A12(2.54,11.43) A13(3.81,11.43) A14(5.08,11.43) A15(6.35,11.43) A16(7.62,11.43) A17(8.89,11.43) A18(10.16,11.43) B1(-11.43,10.16) B2(-10.16,10.16) B3(-8.89,10.16) B4(-7.62,10.16) B5(-6.35,10.16) B6(-5.08,10.16) B7(-3.81,10.16) B8(-2.54,10.16) B9(-1.27,10.16) B10(0,10.16) B11(1.27,10.16) B12(2.54,10.16) B13(3.81,10.16) B14(5.08,10.16) B15(6.35,10.16) B16(7.62,10.16) B17(8.89,10.16) B18(10.16,10.16) B19(11.43,10.16) C1(-11.43,8.89) C2(-10.16,8.89) C3(-8.89,8.89) C4(-7.62,8.89) C5(-6.35,8.89) C6(-5.08,8.89) C7(-3.81,8.89) C8(-2.54,8.89) C9(-1.27,8.89) C10(0,8.89) C11(1.27,8.89) C12(2.54,8.89) C13(3.81,8.89) C14(5.08,8.89) C15(6.35,8.89) C16(7.62,8.89) C17(8.89,8.89) C18(10.16,8.89) C19(11.43,8.89) D1(-11.43,7.62) D2(-10.16,7.62) D3(-8.89,7.62) D7(-3.81,7.62) D8(-2.54,7.62) D9(-1.27,7.62) D10(0,7.62) D11(1.27,7.62) D12(2.54,7.62) D13(3.81,7.62) D17(8.89,7.62) D18(10.16,7.62) D19(11.43,7.62) E1(-11.43,6.35) E2(-10.16,6.35) E3(-8.89,6.35) E17(8.89,6.35) E18(10.16,6.35) E19(11.43,6.35) F1(-11.43,5.08) F2(-10.16,5.08) F3(-8.89,5.08) F17(8.89,5.08) F18(10.16,5.08) F19(11.43,5.08) G1(-11.43,3.81) G2(-10.16,3.81) G3(-8.89,3.81) G4(-7.62,3.81) G16(7.62,3.81) G17(8.89,3.81) G18(10.16,3.81) G19(11.43,3.81) H1(-11.43,2.54) H2(-10.16,2.54) H3(-8.89,2.54) H4(-7.62,2.54) H8(-2.54,2.54) H9(-1.27,2.54) H10(0,2.54) H11(1.27,2.54) H12(2.54,2.54) H16(7.62,2.54) H17(8.89,2.54) H18(10.16,2.54) H19(11.43,2.54) J1(-11.43,1.27) J2(-10.16,1.27) J3(-8.89,1.27) J4(-7.62,1.27) J8(-2.54,1.27) J9(-1.27,1.27) J10(0,1.27) J11(1.27,1.27) J12(2.54,1.27) J16(7.62,1.27) J17(8.89,1.27) J18(10.16,1.27) J19(11.43,1.27) K1(-11.43,0) K2(-10.16,0) K3(-8.89,0) K4(-7.62,0) K8(-2.54,0) K9(-1.27,0) K10(0,0) K11(1.27,0) K12(2.54,0) K16(7.62,0) K17(8.89,0) K18(10.16,0) K19(11.43,0) L1(-11.43,-1.27) L2(-10.16,-1.27) L3(-8.89,-1.27) L4(-7.62,-1.27) L8(-2.54,-1.27) L9(-1.27,-1.27) L10(0,-1.27) L11(1.27,-1.27) L12(2.54,-1.27) L16(7.62,-1.27) L17(8.89,-1.27) L18(10.16,-1.27) L19(11.43,-1.27) M1(-11.43,-2.54) M2(-10.16,-2.54) M3(-8.89,-2.54) M4(-7.62,-2.54) M8(-2.54,-2.54) M9(-1.27,-2.54) M10(0,-2.54) M11(1.27,-2.54) M12(2.54,-2.54) M16(7.62,-2.54) M17(8.89,-2.54) M18(10.16,-2.54) M19(11.43,-2.54) N1(-11.43,-3.81) N2(-10.16,-3.81) N3(-8.89,-3.81) N4(-7.62,-3.81) N16(7.62,-3.81) N17(8.89,-3.81) N18(10.16,-3.81) N19(11.43,-3.81) P1(-11.43,-5.08) P2(-10.16,-5.08) P3(-8.89,-5.08) P17(8.89,-5.08) P18(10.16,-5.08) P19(11.43,-5.08) R1(-11.43,-6.35) R2(-10.16,-6.35) R3(-8.89,-6.35) R17(8.89,-6.35) R18(10.16,-6.35) R19(11.43,-6.35) T1(-11.43,-7.62) T2(-10.16,-7.62) T3(-8.89,-7.62) T7(-3.81,-7.62) T8(-2.54,-7.62) T9(-1.27,-7.62) T10(0,-7.62) T11(1.27,-7.62) T12(2.54,-7.62) T13(3.81,-7.62) T17(8.89,-7.62) T18(10.16,-7.62) T19(11.43,-7.62) U1(-11.43,-8.89) U2(-10.16,-8.89) U3(-8.89,-8.89) U4(-7.62,-8.89) U5(-6.35,-8.89) U6(-5.08,-8.89) U7(-3.81,-8.89) U8(-2.54,-8.89) U9(-1.27,-8.89) U10(0,-8.89) U11(1.27,-8.89) U12(2.54,-8.89) U13(3.81,-8.89) U14(5.08,-8.89) U15(6.35,-8.89) U16(7.62,-8.89) U17(8.89,-8.89) U18(10.16,-8.89) U19(11.43,-8.89) V1(-11.43,-10.16) V2(-10.16,-10.16) V3(-8.89,-10.16) V4(-7.62,-10.16) V5(-6.35,-10.16) V6(-5.08,-10.16) V7(-3.81,-10.16) V8(-2.54,-10.16) V9(-1.27,-10.16) V10(0,-10.16) V11(1.27,-10.16) V12(2.54,-10.16) V13(3.81,-10.16) V14(5.08,-10.16) V15(6.35,-10.16) V16(7.62,-10.16) V17(8.89,-10.16) V18(10.16,-10.16) V19(11.43,-10.16) W2(-10.16,-11.43) W3(-8.89,-11.43) W4(-7.62,-11.43) W5(-6.35,-11.43) W6(-5.08,-11.43) W7(-3.81,-11.43) W8(-2.54,-11.43) W9(-1.27,-11.43) W10(0,-11.43) W11(1.27,-11.43) W12(2.54,-11.43) W13(3.81,-11.43) W14(5.08,-11.43) W15(6.35,-11.43) W16(7.62,-11.43) W17(8.89,-11.43) W18(10.16,-11.43)
Top Overlay:
  circle w0.25: c-13.15,11.43 r0.125
  lines w0.2: -12.5,-11.5 -11.5,-12.5 11.5,-12.5 12.5,-11.5 12.5,11.5 11.5,12.5 -12.5,12.5 -12.5,-11.5

## BGA25X25-B324 [mm]
pads (324):
  round 0.6 smd: A1(-10.795,10.795) A2(-9.525,10.795) A3(-8.255,10.795) A4(-6.985,10.795) A5(-5.715,10.795) A6(-4.445,10.795) A7(-3.175,10.795) A8(-1.905,10.795) A9(-0.635,10.795) A10(0.635,10.795) A11(1.905,10.795) A12(3.175,10.795) A13(4.445,10.795) A14(5.715,10.795) A15(6.985,10.795) A16(8.255,10.795) A17(9.525,10.795) A18(10.795,10.795) B1(-10.795,9.525) B2(-9.525,9.525) B3(-8.255,9.525) B4(-6.985,9.525) B5(-5.715,9.525) B6(-4.445,9.525) B7(-3.175,9.525) B8(-1.905,9.525) B9(-0.635,9.525) B10(0.635,9.525) B11(1.905,9.525) B12(3.175,9.525) B13(4.445,9.525) B14(5.715,9.525) B15(6.985,9.525) B16(8.255,9.525) B17(9.525,9.525) B18(10.795,9.525) C1(-10.795,8.255) C2(-9.525,8.255) C3(-8.255,8.255) C4(-6.985,8.255) C5(-5.715,8.255) C6(-4.445,8.255) C7(-3.175,8.255) C8(-1.905,8.255) C9(-0.635,8.255) C10(0.635,8.255) C11(1.905,8.255) C12(3.175,8.255) C13(4.445,8.255) C14(5.715,8.255) C15(6.985,8.255) C16(8.255,8.255) C17(9.525,8.255) C18(10.795,8.255) D1(-10.795,6.985) D2(-9.525,6.985) D3(-8.255,6.985) D4(-6.985,6.985) D5(-5.715,6.985) D6(-4.445,6.985) D7(-3.175,6.985) D8(-1.905,6.985) D9(-0.635,6.985) D10(0.635,6.985) D11(1.905,6.985) D12(3.175,6.985) D13(4.445,6.985) D14(5.715,6.985) D15(6.985,6.985) D16(8.255,6.985) D17(9.525,6.985) D18(10.795,6.985) E1(-10.795,5.715) E2(-9.525,5.715) E3(-8.255,5.715) E4(-6.985,5.715) E5(-5.715,5.715) E6(-4.445,5.715) E7(-3.175,5.715) E8(-1.905,5.715) E9(-0.635,5.715) E10(0.635,5.715) E11(1.905,5.715) E12(3.175,5.715) E13(4.445,5.715) E14(5.715,5.715) E15(6.985,5.715) E16(8.255,5.715) E17(9.525,5.715) E18(10.795,5.715) F1(-10.795,4.445) F2(-9.525,4.445) F3(-8.255,4.445) F4(-6.985,4.445) F5(-5.715,4.445) F6(-4.445,4.445) F7(-3.175,4.445) F8(-1.905,4.445) F9(-0.635,4.445) F10(0.635,4.445) F11(1.905,4.445) F12(3.175,4.445) F13(4.445,4.445) F14(5.715,4.445) F15(6.985,4.445) F16(8.255,4.445) F17(9.525,4.445) F18(10.795,4.445) G1(-10.795,3.175) G2(-9.525,3.175) G3(-8.255,3.175) G4(-6.985,3.175) G5(-5.715,3.175) G6(-4.445,3.175) G7(-3.175,3.175) G8(-1.905,3.175) G9(-0.635,3.175) G10(0.635,3.175) G11(1.905,3.175) G12(3.175,3.175) G13(4.445,3.175) G14(5.715,3.175) G15(6.985,3.175) G16(8.255,3.175) G17(9.525,3.175) G18(10.795,3.175) H1(-10.795,1.905) H2(-9.525,1.905) H3(-8.255,1.905) H4(-6.985,1.905) H5(-5.715,1.905) H6(-4.445,1.905) H7(-3.175,1.905) H8(-1.905,1.905) H9(-0.635,1.905) H10(0.635,1.905) H11(1.905,1.905) H12(3.175,1.905) H13(4.445,1.905) H14(5.715,1.905) H15(6.985,1.905) H16(8.255,1.905) H17(9.525,1.905) H18(10.795,1.905) J1(-10.795,0.635) J2(-9.525,0.635) J3(-8.255,0.635) J4(-6.985,0.635) J5(-5.715,0.635) J6(-4.445,0.635) J7(-3.175,0.635) J8(-1.905,0.635) J9(-0.635,0.635) J10(0.635,0.635) J11(1.905,0.635) J12(3.175,0.635) J13(4.445,0.635) J14(5.715,0.635) J15(6.985,0.635) J16(8.255,0.635) J17(9.525,0.635) J18(10.795,0.635) K1(-10.795,-0.635) K2(-9.525,-0.635) K3(-8.255,-0.635) K4(-6.985,-0.635) K5(-5.715,-0.635) K6(-4.445,-0.635) K7(-3.175,-0.635) K8(-1.905,-0.635) K9(-0.635,-0.635) K10(0.635,-0.635) K11(1.905,-0.635) K12(3.175,-0.635) K13(4.445,-0.635) K14(5.715,-0.635) K15(6.985,-0.635) K16(8.255,-0.635) K17(9.525,-0.635) K18(10.795,-0.635) L1(-10.795,-1.905) L2(-9.525,-1.905) L3(-8.255,-1.905) L4(-6.985,-1.905) L5(-5.715,-1.905) L6(-4.445,-1.905) L7(-3.175,-1.905) L8(-1.905,-1.905) L9(-0.635,-1.905) L10(0.635,-1.905) L11(1.905,-1.905) L12(3.175,-1.905) L13(4.445,-1.905) L14(5.715,-1.905) L15(6.985,-1.905) L16(8.255,-1.905) L17(9.525,-1.905) L18(10.795,-1.905) M1(-10.795,-3.175) M2(-9.525,-3.175) M3(-8.255,-3.175) M4(-6.985,-3.175) M5(-5.715,-3.175) M6(-4.445,-3.175) M7(-3.175,-3.175) M8(-1.905,-3.175) M9(-0.635,-3.175) M10(0.635,-3.175) M11(1.905,-3.175) M12(3.175,-3.175) M13(4.445,-3.175) M14(5.715,-3.175) M15(6.985,-3.175) M16(8.255,-3.175) M17(9.525,-3.175) M18(10.795,-3.175) N1(-10.795,-4.445) N2(-9.525,-4.445) N3(-8.255,-4.445) N4(-6.985,-4.445) N5(-5.715,-4.445) N6(-4.445,-4.445) N7(-3.175,-4.445) N8(-1.905,-4.445) N9(-0.635,-4.445) N10(0.635,-4.445) N11(1.905,-4.445) N12(3.175,-4.445) N13(4.445,-4.445) N14(5.715,-4.445) N15(6.985,-4.445) N16(8.255,-4.445) N17(9.525,-4.445) N18(10.795,-4.445) P1(-10.795,-5.715) P2(-9.525,-5.715) P3(-8.255,-5.715) P4(-6.985,-5.715) P5(-5.715,-5.715) P6(-4.445,-5.715) P7(-3.175,-5.715) P8(-1.905,-5.715) P9(-0.635,-5.715) P10(0.635,-5.715) P11(1.905,-5.715) P12(3.175,-5.715) P13(4.445,-5.715) P14(5.715,-5.715) P15(6.985,-5.715) P16(8.255,-5.715) P17(9.525,-5.715) P18(10.795,-5.715) R1(-10.795,-6.985) R2(-9.525,-6.985) R3(-8.255,-6.985) R4(-6.985,-6.985) R5(-5.715,-6.985) R6(-4.445,-6.985) R7(-3.175,-6.985) R8(-1.905,-6.985) R9(-0.635,-6.985) R10(0.635,-6.985) R11(1.905,-6.985) R12(3.175,-6.985) R13(4.445,-6.985) R14(5.715,-6.985) R15(6.985,-6.985) R16(8.255,-6.985) R17(9.525,-6.985) R18(10.795,-6.985) T1(-10.795,-8.255) T2(-9.525,-8.255) T3(-8.255,-8.255) T4(-6.985,-8.255) T5(-5.715,-8.255) T6(-4.445,-8.255) T7(-3.175,-8.255) T8(-1.905,-8.255) T9(-0.635,-8.255) T10(0.635,-8.255) T11(1.905,-8.255) T12(3.175,-8.255) T13(4.445,-8.255) T14(5.715,-8.255) T15(6.985,-8.255) T16(8.255,-8.255) T17(9.525,-8.255) T18(10.795,-8.255) U1(-10.795,-9.525) U2(-9.525,-9.525) U3(-8.255,-9.525) U4(-6.985,-9.525) U5(-5.715,-9.525) U6(-4.445,-9.525) U7(-3.175,-9.525) U8(-1.905,-9.525) U9(-0.635,-9.525) U10(0.635,-9.525) U11(1.905,-9.525) U12(3.175,-9.525) U13(4.445,-9.525) U14(5.715,-9.525) U15(6.985,-9.525) U16(8.255,-9.525) U17(9.525,-9.525) U18(10.795,-9.525) V1(-10.795,-10.795) V2(-9.525,-10.795) V3(-8.255,-10.795) V4(-6.985,-10.795) V5(-5.715,-10.795) V6(-4.445,-10.795) V7(-3.175,-10.795) V8(-1.905,-10.795) V9(-0.635,-10.795) V10(0.635,-10.795) V11(1.905,-10.795) V12(3.175,-10.795) V13(4.445,-10.795) V14(5.715,-10.795) V15(6.985,-10.795) V16(8.255,-10.795) V17(9.525,-10.795) V18(10.795,-10.795)
Top Overlay:
  circle w0.25: c-13.15,10.795 r0.125
  lines w0.2: -12.495,-11.505 -11.495,-12.505 11.505,-12.505 12.505,-11.505 12.505,11.495 11.505,12.495 -12.495,12.495 -12.495,-11.505

## BGA25X25-B357 [mm]
pads (357):
  round 0.6 smd: A2(-10.16,11.43) A3(-8.89,11.43) A4(-7.62,11.43) A5(-6.35,11.43) A6(-5.08,11.43) A7(-3.81,11.43) A8(-2.54,11.43) A9(-1.27,11.43) A10(0,11.43) A11(1.27,11.43) A12(2.54,11.43) A13(3.81,11.43) A14(5.08,11.43) A15(6.35,11.43) A16(7.62,11.43) A17(8.89,11.43) A18(10.16,11.43) B1(-11.43,10.16) B2(-10.16,10.16) B3(-8.89,10.16) B4(-7.62,10.16) B5(-6.35,10.16) B6(-5.08,10.16) B7(-3.81,10.16) B8(-2.54,10.16) B9(-1.27,10.16) B10(0,10.16) B11(1.27,10.16) B12(2.54,10.16) B13(3.81,10.16) B14(5.08,10.16) B15(6.35,10.16) B16(7.62,10.16) B17(8.89,10.16) B18(10.16,10.16) B19(11.43,10.16) C1(-11.43,8.89) C2(-10.16,8.89) C3(-8.89,8.89) C4(-7.62,8.89) C5(-6.35,8.89) C6(-5.08,8.89) C7(-3.81,8.89) C8(-2.54,8.89) C9(-1.27,8.89) C10(0,8.89) C11(1.27,8.89) C12(2.54,8.89) C13(3.81,8.89) C14(5.08,8.89) C15(6.35,8.89) C16(7.62,8.89) C17(8.89,8.89) C18(10.16,8.89) C19(11.43,8.89) D1(-11.43,7.62) D2(-10.16,7.62) D3(-8.89,7.62) D4(-7.62,7.62) D5(-6.35,7.62) D6(-5.08,7.62) D7(-3.81,7.62) D8(-2.54,7.62) D9(-1.27,7.62) D10(0,7.62) D11(1.27,7.62) D12(2.54,7.62) D13(3.81,7.62) D14(5.08,7.62) D15(6.35,7.62) D16(7.62,7.62) D17(8.89,7.62) D18(10.16,7.62) D19(11.43,7.62) E1(-11.43,6.35) E2(-10.16,6.35) E3(-8.89,6.35) E4(-7.62,6.35) E5(-6.35,6.35) E6(-5.08,6.35) E7(-3.81,6.35) E8(-2.54,6.35) E9(-1.27,6.35) E10(0,6.35) E11(1.27,6.35) E12(2.54,6.35) E13(3.81,6.35) E14(5.08,6.35) E15(6.35,6.35) E16(7.62,6.35) E17(8.89,6.35) E18(10.16,6.35) E19(11.43,6.35) F1(-11.43,5.08) F2(-10.16,5.08) F3(-8.89,5.08) F4(-7.62,5.08) F5(-6.35,5.08) F6(-5.08,5.08) F7(-3.81,5.08) F8(-2.54,5.08) F9(-1.27,5.08) F10(0,5.08) F11(1.27,5.08) F12(2.54,5.08) F13(3.81,5.08) F14(5.08,5.08) F15(6.35,5.08) F16(7.62,5.08) F17(8.89,5.08) F18(10.16,5.08) F19(11.43,5.08) G1(-11.43,3.81) G2(-10.16,3.81) G3(-8.89,3.81) G4(-7.62,3.81) G5(-6.35,3.81) G6(-5.08,3.81) G7(-3.81,3.81) G8(-2.54,3.81) G9(-1.27,3.81) G10(0,3.81) G11(1.27,3.81) G12(2.54,3.81) G13(3.81,3.81) G14(5.08,3.81) G15(6.35,3.81) G16(7.62,3.81) G17(8.89,3.81) G18(10.16,3.81) G19(11.43,3.81) H1(-11.43,2.54) H2(-10.16,2.54) H3(-8.89,2.54) H4(-7.62,2.54) H5(-6.35,2.54) H6(-5.08,2.54) H7(-3.81,2.54) H8(-2.54,2.54) H9(-1.27,2.54) H10(0,2.54) H11(1.27,2.54) H12(2.54,2.54) H13(3.81,2.54) H14(5.08,2.54) H15(6.35,2.54) H16(7.62,2.54) H17(8.89,2.54) H18(10.16,2.54) H19(11.43,2.54) J1(-11.43,1.27) J2(-10.16,1.27) J3(-8.89,1.27) J4(-7.62,1.27) J5(-6.35,1.27) J6(-5.08,1.27) J7(-3.81,1.27) J8(-2.54,1.27) J9(-1.27,1.27) J10(0,1.27) J11(1.27,1.27) J12(2.54,1.27) J13(3.81,1.27) J14(5.08,1.27) J15(6.35,1.27) J16(7.62,1.27) J17(8.89,1.27) J18(10.16,1.27) J19(11.43,1.27) K1(-11.43,0) K2(-10.16,0) K3(-8.89,0) K4(-7.62,0) K5(-6.35,0) K6(-5.08,0) K7(-3.81,0) K8(-2.54,0) K9(-1.27,0) K10(0,0) K11(1.27,0) K12(2.54,0) K13(3.81,0) K14(5.08,0) K15(6.35,0) K16(7.62,0) K17(8.89,0) K18(10.16,0) K19(11.43,0) L1(-11.43,-1.27) L2(-10.16,-1.27) L3(-8.89,-1.27) L4(-7.62,-1.27) L5(-6.35,-1.27) L6(-5.08,-1.27) L7(-3.81,-1.27) L8(-2.54,-1.27) L9(-1.27,-1.27) L10(0,-1.27) L11(1.27,-1.27) L12(2.54,-1.27) L13(3.81,-1.27) L14(5.08,-1.27) L15(6.35,-1.27) L16(7.62,-1.27) L17(8.89,-1.27) L18(10.16,-1.27) L19(11.43,-1.27) M1(-11.43,-2.54) M2(-10.16,-2.54) M3(-8.89,-2.54) M4(-7.62,-2.54) M5(-6.35,-2.54) M6(-5.08,-2.54) M7(-3.81,-2.54) M8(-2.54,-2.54) M9(-1.27,-2.54) M10(0,-2.54) M11(1.27,-2.54) M12(2.54,-2.54) M13(3.81,-2.54) M14(5.08,-2.54) M15(6.35,-2.54) M16(7.62,-2.54) M17(8.89,-2.54) M18(10.16,-2.54) M19(11.43,-2.54) N1(-11.43,-3.81) N2(-10.16,-3.81) N3(-8.89,-3.81) N4(-7.62,-3.81) N5(-6.35,-3.81) N6(-5.08,-3.81) N7(-3.81,-3.81) N8(-2.54,-3.81) N9(-1.27,-3.81) N10(0,-3.81) N11(1.27,-3.81) N12(2.54,-3.81) N13(3.81,-3.81) N14(5.08,-3.81) N15(6.35,-3.81) N16(7.62,-3.81) N17(8.89,-3.81) N18(10.16,-3.81) N19(11.43,-3.81) P1(-11.43,-5.08) P2(-10.16,-5.08) P3(-8.89,-5.08) P4(-7.62,-5.08) P5(-6.35,-5.08) P6(-5.08,-5.08) P7(-3.81,-5.08) P8(-2.54,-5.08) P9(-1.27,-5.08) P10(0,-5.08) P11(1.27,-5.08) P12(2.54,-5.08) P13(3.81,-5.08) P14(5.08,-5.08) P15(6.35,-5.08) P16(7.62,-5.08) P17(8.89,-5.08) P18(10.16,-5.08) P19(11.43,-5.08) R1(-11.43,-6.35) R2(-10.16,-6.35) R3(-8.89,-6.35) R4(-7.62,-6.35) R5(-6.35,-6.35) R6(-5.08,-6.35) R7(-3.81,-6.35) R8(-2.54,-6.35) R9(-1.27,-6.35) R10(0,-6.35) R11(1.27,-6.35) R12(2.54,-6.35) R13(3.81,-6.35) R14(5.08,-6.35) R15(6.35,-6.35) R16(7.62,-6.35) R17(8.89,-6.35) R18(10.16,-6.35) R19(11.43,-6.35) S1(-11.43,-7.62) S2(-10.16,-7.62) S3(-8.89,-7.62) S4(-7.62,-7.62) S5(-6.35,-7.62) S6(-5.08,-7.62) S7(-3.81,-7.62) S8(-2.54,-7.62) S9(-1.27,-7.62) S10(0,-7.62) S11(1.27,-7.62) S12(2.54,-7.62) S13(3.81,-7.62) S14(5.08,-7.62) S15(6.35,-7.62) S16(7.62,-7.62) S17(8.89,-7.62) S18(10.16,-7.62) S19(11.43,-7.62) T1(-11.43,-8.89) T2(-10.16,-8.89) T3(-8.89,-8.89) T4(-7.62,-8.89) T5(-6.35,-8.89) T6(-5.08,-8.89) T7(-3.81,-8.89) T8(-2.54,-8.89) T9(-1.27,-8.89) T10(0,-8.89) T11(1.27,-8.89) T12(2.54,-8.89) T13(3.81,-8.89) T14(5.08,-8.89) T15(6.35,-8.89) T16(7.62,-8.89) T17(8.89,-8.89) T18(10.16,-8.89) T19(11.43,-8.89) U1(-11.43,-10.16) U2(-10.16,-10.16) U3(-8.89,-10.16) U4(-7.62,-10.16) U5(-6.35,-10.16) U6(-5.08,-10.16) U7(-3.81,-10.16) U8(-2.54,-10.16) U9(-1.27,-10.16) U10(0,-10.16) U11(1.27,-10.16) U12(2.54,-10.16) U13(3.81,-10.16) U14(5.08,-10.16) U15(6.35,-10.16) U16(7.62,-10.16) U17(8.89,-10.16) U18(10.16,-10.16) U19(11.43,-10.16) V2(-10.16,-11.43) V3(-8.89,-11.43) V4(-7.62,-11.43) V5(-6.35,-11.43) V6(-5.08,-11.43) V7(-3.81,-11.43) V8(-2.54,-11.43) V9(-1.27,-11.43) V10(0,-11.43) V11(1.27,-11.43) V12(2.54,-11.43) V13(3.81,-11.43) V14(5.08,-11.43) V15(6.35,-11.43) V16(7.62,-11.43) V17(8.89,-11.43) V18(10.16,-11.43)
Top Overlay:
  circle w0.25: c-13.15,11.43 r0.125
  lines w0.2: -12.5,-11.5 -12.5,12.5 11.5,12.5 12.5,11.5 12.5,-11.5 11.5,-12.5 -11.5,-12.5 -12.5,-11.5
